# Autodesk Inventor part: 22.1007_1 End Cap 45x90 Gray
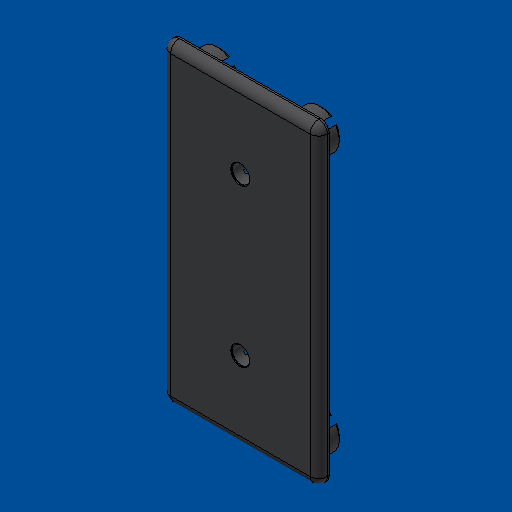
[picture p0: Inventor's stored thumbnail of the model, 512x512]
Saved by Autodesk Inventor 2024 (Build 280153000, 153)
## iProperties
Created: 2012-02
Part Number: 22.1007_1 End Cap 45x90 Gray
Document SubType Name: Modeling
Designer: Administrator
Density: 1.06 g/cm^3
Material: ABS Plastic
Mass: 10.9481 g
Surface Area: 108.264 cm^2
Volume: 10.3284 cm^3
Appearance: Gray
Author: Administrator
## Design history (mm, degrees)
feature "Base1"
body "Solid1"
